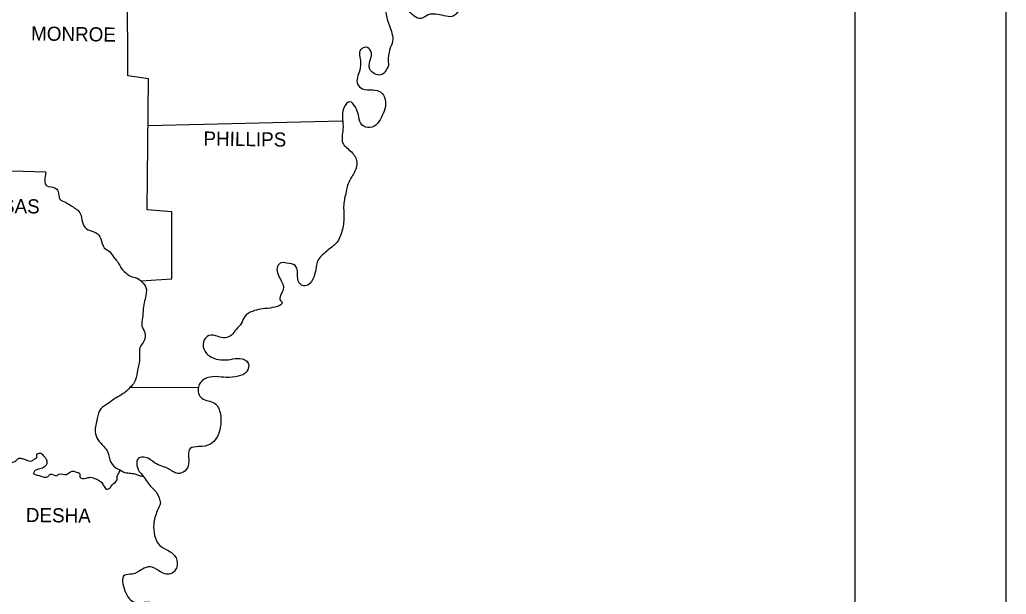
# Model space of a CAD drawing. Extents: x -0.54 to 1.64, y 0 to 0.92.
# Drawn here: x 1.2805 to 1.4167, y 0.624 to 0.7032 of the extents above; entities that cross this region are included whole.
import ezdxf

# ---------------------------------------------------------------- set-up
doc = ezdxf.new("R2010")
doc.units = 0
doc.layers.add('SHET_Annotations', color=7, linetype='Continuous')
doc.layers.add('SHET_Border-Lines', color=7, linetype='Continuous')

msp = doc.modelspace()

# ---------------------------------------------------------------- linework, layer by layer
at = {"layer": 'SHET_Annotations'}
for p, q in [((1.2958, 0.65251), (1.3052, 0.65256)), ((1.2958, 0.65251), (1.3052, 0.65256)), ((1.29742, 0.64027), (1.29756, 0.64027))]:
    msp.add_line(p, q, dxfattribs=at)
for points in [[(1.29727, 0.6672), (1.30154, 0.66747), (1.30152, 0.67671), (1.29814, 0.67697), (1.29833, 0.69507), (1.29547, 0.69548), (1.2954, 0.70767), (1.3345, 0.70793)], [(1.29826, 0.68863), (1.3251, 0.68928)], [(1.28417, 0.68218), (1.26689, 0.68267), (1.26679, 0.67704), (1.23188, 0.67691)]]:
    msp.add_lwpolyline(points, dxfattribs=at)
for points in [[(1.35126, 0.74211), (1.35144, 0.74082), (1.35064, 0.73939), (1.35035, 0.73799), (1.35051, 0.73656), (1.34905, 0.73578), (1.34776, 0.73485), (1.34851, 0.73379), (1.34986, 0.73275), (1.35123, 0.732), (1.35209, 0.73119), (1.35235, 0.72935), (1.35258, 0.72813), (1.35302, 0.72653), (1.3532, 0.72536), (1.3524, 0.72401), (1.35144, 0.72373), (1.3504, 0.72406), (1.34921, 0.72414), (1.34825, 0.72321), (1.34758, 0.72196), (1.3469, 0.72067), (1.34638, 0.71958), (1.34589, 0.71841), (1.34488, 0.71703), (1.34366, 0.7168), (1.34218, 0.71644), (1.34133, 0.71543), (1.34145, 0.71374), (1.34228, 0.71257), (1.34293, 0.71117), (1.3434, 0.70993), (1.34314, 0.7084), (1.34252, 0.70726), (1.34171, 0.70656), (1.34133, 0.7051), (1.34075, 0.70402), (1.34018, 0.70365), (1.33909, 0.70376), (1.33793, 0.70396), (1.33692, 0.70389), (1.33593, 0.70337), (1.33497, 0.7037), (1.33399, 0.70477), (1.33318, 0.7056), (1.33225, 0.70591), (1.33129, 0.70542), (1.33111, 0.70391), (1.33155, 0.70236), (1.33199, 0.70025), (1.33157, 0.69901), (1.33142, 0.69688)], [(1.33142, 0.69688), (1.33038, 0.69559), (1.32885, 0.69639), (1.32885, 0.69748), (1.32906, 0.69865), (1.32851, 0.69937), (1.32755, 0.69906), (1.32755, 0.69764), (1.32745, 0.69624), (1.32716, 0.69432), (1.32784, 0.69369), (1.32927, 0.69354), (1.33035, 0.69323), (1.33098, 0.69222), (1.33093, 0.69092), (1.33041, 0.6897), (1.32968, 0.68869), (1.32857, 0.68833), (1.32763, 0.6889), (1.32727, 0.69011), (1.32688, 0.69113), (1.32608, 0.6919), (1.32527, 0.69107), (1.32509, 0.68947), (1.32514, 0.68809), (1.32512, 0.6862), (1.32631, 0.68498), (1.32706, 0.68358), (1.3268, 0.68231), (1.32595, 0.68078), (1.32558, 0.67948), (1.32525, 0.67767), (1.32527, 0.67572), (1.32493, 0.6738), (1.32431, 0.67251), (1.32312, 0.67147), (1.32234, 0.67079), (1.32172, 0.67009), (1.32138, 0.66872), (1.32115, 0.66779), (1.32029, 0.66662), (1.31959, 0.66654), (1.31905, 0.66701), (1.31889, 0.66779), (1.31887, 0.66854), (1.31853, 0.66932), (1.31739, 0.66965), (1.31648, 0.66963), (1.31607, 0.66898), (1.31664, 0.66719), (1.3169, 0.66605), (1.31653, 0.66449), (1.31671, 0.66431), (1.31511, 0.66345), (1.31376, 0.6633), (1.31267, 0.66299), (1.3116, 0.66229), (1.31111, 0.6613), (1.31039, 0.6605), (1.30976, 0.65972), (1.30888, 0.65936), (1.30792, 0.65951), (1.30665, 0.65967), (1.3059, 0.65876), (1.30613, 0.65744), (1.30701, 0.65666), (1.30831, 0.6563), (1.30963, 0.65637), (1.3109, 0.6565), (1.31207, 0.65586), (1.31184, 0.65464), (1.3107, 0.65404), (1.30901, 0.65388), (1.30764, 0.65399), (1.306, 0.65363), (1.3052, 0.65256), (1.30567, 0.65101), (1.30743, 0.65033), (1.30823, 0.64883), (1.30828, 0.64743), (1.30769, 0.64553), (1.30686, 0.64468), (1.30528, 0.64434), (1.30406, 0.64408), (1.30385, 0.64198), (1.30333, 0.64097), (1.30237, 0.64063), (1.301, 0.64133), (1.30017, 0.64164), (1.29916, 0.64211), (1.29791, 0.64286), (1.29693, 0.64273), (1.29721, 0.64071), (1.29729, 0.64063), (1.2984, 0.6391), (1.29947, 0.63794), (1.29999, 0.63653)], [(1.28417, 0.68218), (1.2843, 0.68031), (1.2854, 0.68003), (1.28585, 0.67953), (1.28608, 0.67848), (1.28686, 0.67803), (1.28791, 0.67739), (1.28855, 0.67693), (1.289, 0.6762), (1.28928, 0.67501), (1.29001, 0.67424), (1.29101, 0.67387), (1.29174, 0.67301), (1.2922, 0.67177), (1.29293, 0.67123), (1.29366, 0.67027), (1.29402, 0.66986), (1.29466, 0.66876), (1.2953, 0.66821), (1.29576, 0.66789), (1.29649, 0.66767), (1.2974, 0.66707), (1.29799, 0.66616), (1.29799, 0.66548), (1.29777, 0.66443), (1.29758, 0.66333), (1.29749, 0.6621), (1.2974, 0.661), (1.29781, 0.66009), (1.29758, 0.65872), (1.29713, 0.65799), (1.29708, 0.65699), (1.29694, 0.65548), (1.29676, 0.65461), (1.29635, 0.6532), (1.2958, 0.65251)], [(1.28417, 0.68218), (1.2843, 0.68031), (1.2854, 0.68003), (1.28585, 0.67953), (1.28608, 0.67848), (1.28686, 0.67803), (1.28791, 0.67739), (1.28855, 0.67693), (1.289, 0.6762), (1.28928, 0.67501), (1.29001, 0.67424), (1.29101, 0.67387), (1.29174, 0.67301), (1.2922, 0.67177), (1.29293, 0.67123), (1.29366, 0.67027), (1.29402, 0.66986), (1.29466, 0.66876), (1.2953, 0.66821), (1.29576, 0.66789), (1.29649, 0.66767), (1.2974, 0.66707), (1.29799, 0.66616), (1.29799, 0.66548), (1.29777, 0.66443), (1.29758, 0.66333), (1.29749, 0.6621), (1.2974, 0.661), (1.29781, 0.66009), (1.29758, 0.65872), (1.29713, 0.65799), (1.29708, 0.65699), (1.29694, 0.65548), (1.29676, 0.65461), (1.29635, 0.6532), (1.29576, 0.65247)], [(1.26679, 0.6586), (1.26752, 0.65814), (1.26848, 0.65819), (1.26907, 0.65845), (1.26962, 0.65842), (1.27027, 0.65801), (1.27076, 0.65749), (1.27107, 0.65707), (1.27128, 0.6564), (1.27128, 0.65583), (1.27151, 0.655), (1.2718, 0.65466), (1.27213, 0.65409), (1.27239, 0.65352), (1.2725, 0.65318), (1.27301, 0.65256), (1.27348, 0.65264), (1.27387, 0.65256), (1.27444, 0.65225), (1.27524, 0.65163), (1.2754, 0.65142), (1.27592, 0.65025), (1.27602, 0.64953), (1.2761, 0.64857), (1.27628, 0.64766), (1.27667, 0.64665), (1.27685, 0.64597), (1.27727, 0.64502), (1.27755, 0.64437), (1.27792, 0.64356), (1.27843, 0.64263), (1.27869, 0.64208), (1.27947, 0.64214), (1.27999, 0.64237), (1.28041, 0.64273), (1.28092, 0.64268), (1.28144, 0.6425), (1.2822, 0.64237), (1.28264, 0.64266), (1.2829, 0.64284), (1.28292, 0.64323), (1.28334, 0.64346), (1.2838, 0.64312), (1.28427, 0.6424), (1.28427, 0.64195), (1.28409, 0.64167), (1.28352, 0.64131), (1.28269, 0.64105), (1.28245, 0.64071), (1.28323, 0.64035), (1.28445, 0.64024), (1.28479, 0.64055), (1.28562, 0.64032), (1.28593, 0.64053), (1.28702, 0.6405), (1.28754, 0.64087), (1.28852, 0.64079), (1.28883, 0.64058), (1.28883, 0.64019), (1.28969, 0.63998), (1.29029, 0.64011), (1.29104, 0.63988), (1.29171, 0.63952), (1.29208, 0.63902), (1.29254, 0.63848), (1.29296, 0.63861), (1.29329, 0.63905), (1.29397, 0.63978), (1.29397, 0.64022), (1.29412, 0.64053), (1.29443, 0.6411)], [(1.29576, 0.65247), (1.29448, 0.65142), (1.29366, 0.65096), (1.29279, 0.65032), (1.29174, 0.64955), (1.29124, 0.64822), (1.29097, 0.6464), (1.29133, 0.6453), (1.29215, 0.64434), (1.2927, 0.64357), (1.29311, 0.6422), (1.29412, 0.64124), (1.29443, 0.6411)], [(1.29443, 0.6411), (1.2949, 0.64084), (1.29568, 0.64068), (1.29641, 0.64058), (1.29693, 0.64042), (1.29716, 0.64032), (1.29742, 0.64027)], [(1.29999, 0.63653), (1.29952, 0.63547), (1.29903, 0.63366), (1.29916, 0.6321), (1.29983, 0.63075), (1.30095, 0.63005), (1.30211, 0.62901), (1.30206, 0.62738), (1.30136, 0.62678), (1.29975, 0.6272), (1.29853, 0.62777), (1.29747, 0.62743), (1.29604, 0.62676), (1.29503, 0.6266), (1.29506, 0.62445), (1.29646, 0.62287), (1.2977, 0.62287), (1.29913, 0.62271), (1.29962, 0.62105), (1.29879, 0.6197), (1.29742, 0.61898), (1.29571, 0.61981), (1.29449, 0.62069), (1.29322, 0.62152), (1.29169, 0.62193), (1.29081, 0.62175), (1.29042, 0.61983), (1.29114, 0.6181), (1.29234, 0.61688), (1.29342, 0.61535), (1.29324, 0.61421), (1.29241, 0.61389), (1.29096, 0.61358), (1.29008, 0.61309), (1.28987, 0.61275), (1.29031, 0.6112), (1.29073, 0.60949), (1.29073, 0.60821), (1.29023, 0.60702), (1.28946, 0.60521), (1.28953, 0.60404), (1.29008, 0.60347), (1.29078, 0.60368), (1.29169, 0.6043), (1.29226, 0.60505), (1.29278, 0.60593), (1.29374, 0.60671), (1.2949, 0.60604), (1.29521, 0.60464), (1.29451, 0.60339), (1.29355, 0.60285), (1.29239, 0.60241), (1.29148, 0.60139), (1.29171, 0.6002), (1.29241, 0.59958), (1.2941, 0.59986), (1.29524, 0.60036), (1.29586, 0.60103), (1.29664, 0.60181), (1.29706, 0.60256), (1.29765, 0.60339), (1.29872, 0.60362), (1.29921, 0.60292), (1.29903, 0.60139), (1.29838, 0.59994), (1.29752, 0.59867), (1.29656, 0.59781), (1.2954, 0.59595), (1.29563, 0.59421), (1.29604, 0.59278), (1.29669, 0.59169), (1.29778, 0.59193), (1.29903, 0.59208), (1.29978, 0.59149), (1.29967, 0.59022), (1.29874, 0.58897), (1.29791, 0.5878), (1.29744, 0.58612), (1.29763, 0.58498), (1.29763, 0.58394), (1.29724, 0.5828), (1.29659, 0.58215), (1.29493, 0.58223), (1.29317, 0.58241), (1.29218, 0.58187), (1.29236, 0.58028), (1.29342, 0.57917), (1.29415, 0.57857), (1.29519, 0.57727), (1.29565, 0.57624), (1.2955, 0.57533), (1.29488, 0.57455), (1.29301, 0.57362)]]:
    msp.add_spline(points, degree=3, dxfattribs=at)
at = {"layer": 'SHET_Border-Lines'}
for points in [[(0, 0), (1.41667, 0), (1.41667, 0.91667), (0, 0.91667)], [(0.04167, 0.02083), (1.39583, 0.02083), (1.39583, 0.89583), (0.04167, 0.89583)]]:
    msp.add_lwpolyline(points, close=True, dxfattribs=at)

# ---------------------------------------------------------------- texts
at = {"layer": 'SHET_Annotations'}
for s, rotation, p in [('MONROE', 359.1697, (1.2821, 0.70035)), ('PHILLIPS', 359.217, (1.30589, 0.68586)), ('ARKANSAS', 359.2655, (1.26913, 0.67667)), ('DESHA', 359.2949, (1.28138, 0.63395))]:
    msp.add_text(s, height=0.001945, rotation=rotation, dxfattribs=at).set_placement(p)

doc.saveas('drawing.dxf')
